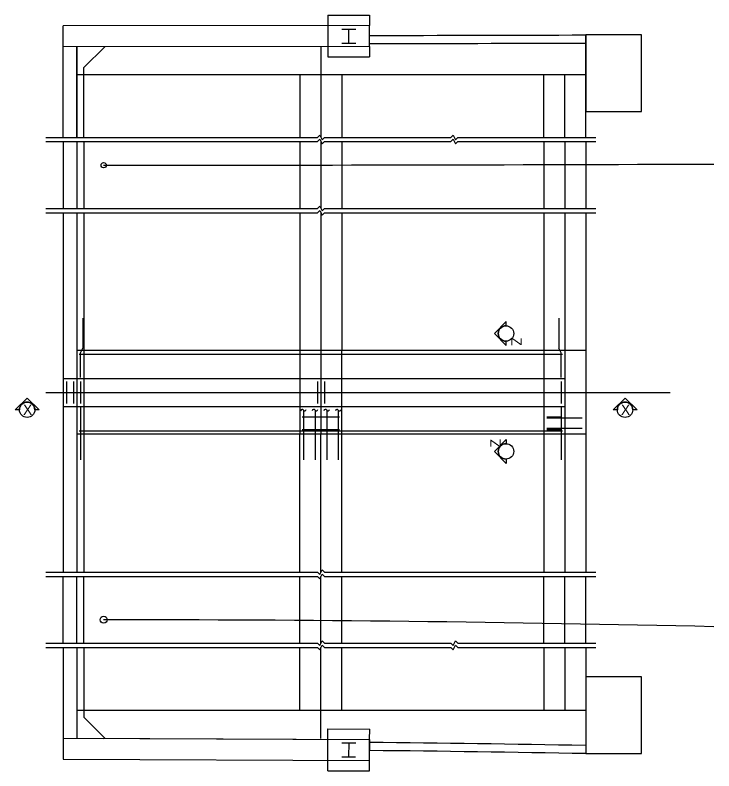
# Model space of a CAD drawing. Extents: x 1531 to 2925, y 1224 to 1658.
# Drawn here: x 2213.3 to 2263.4, y 1437.7 to 1491.9 of the extents above; entities that cross this region are included whole.
import ezdxf

# ---------------------------------------------------------------- set-up
doc = ezdxf.new("R2010")
doc.units = 0
for name, color, linetype in [('B_Border', 7, 'Continuous'), ('B_Reference_Clip', 7, 'Continuous'), ('BD-EXIST-COSS', 7, 'Continuous'), ('R_Border Prem', 7, 'Continuous'), ('R_Draft', 7, 'Continuous'), ('R_Guard Rail', 7, 'Continuous'), ('R_ROW_COA', 7, 'Continuous'), ('R_Survey Control', 7, 'Continuous'), ('R_Wall', 7, 'Continuous')]:
    doc.layers.add(name, color=color, linetype=linetype)

msp = doc.modelspace()

# ---------------------------------------------------------------- linework, layer by layer
at = {"layer": 'B_Border'}
msp.add_line((2215.527, 1464.865), (2260.321, 1464.865), dxfattribs=at)
at = {"layer": 'B_Reference_Clip'}
for points in [[(2258.25, 1490.511), (2254.25, 1490.511), (2254.25, 1485.011), (2258.25, 1485.011)], [(2258.25, 1444.457), (2254.25, 1444.457), (2254.25, 1438.957), (2258.25, 1438.957)]]:
    msp.add_lwpolyline(points, close=True, dxfattribs=at)
at = {"layer": 'BD-EXIST-COSS'}
for p, q in [((2218.167, 1470.199), (2218.167, 1468.032)), ((2252.333, 1470.199), (2252.333, 1468.032)), ((2217.917, 1467.615), (2252.583, 1467.615)), ((2218, 1467.699), (2218.167, 1468.032)), ((2218, 1465.949), (2218, 1467.699)), ((2252.5, 1467.699), (2252.333, 1468.032)), ((2252.5, 1465.949), (2252.5, 1467.699)), ((2217, 1465.647), (2217, 1464.084)), ((2217.5, 1465.647), (2217.5, 1464.084)), ((2218, 1465.647), (2218, 1464.084)), ((2235, 1465.647), (2235, 1464.084)), ((2235.5, 1465.647), (2235.5, 1464.084)), ((2252.5, 1465.647), (2252.5, 1464.084)), ((2218, 1463.782), (2218, 1460.032)), ((2234, 1463.6), (2234, 1460.032)), ((2234.833, 1463.6), (2234.833, 1460.032)), ((2235.667, 1463.6), (2235.667, 1460.032)), ((2236.5, 1463.6), (2236.5, 1460.032)), ((2252.5, 1463.782), (2252.5, 1460.032)), ((2233.917, 1463.115), (2236.583, 1463.115)), ((2251.458, 1463.115), (2252.542, 1463.115)), ((2251.458, 1463.032), (2254, 1463.032)), ((2233.917, 1462.215), (2236.583, 1462.215)), ((2251.458, 1462.299), (2254, 1462.299)), ((2251.458, 1462.215), (2252.542, 1462.215)), ((2217.917, 1462.115), (2252.583, 1462.115))]:
    msp.add_line(p, q, dxfattribs=at)
for centre, start, end in [((2233.907, 1463.546), 30.2608, 174.7876), ((2234.093, 1463.654), 210.2606, 354.7867), ((2234.741, 1463.546), 30.2608, 174.7876), ((2234.926, 1463.654), 210.2606, 354.7867), ((2235.574, 1463.546), 30.2608, 174.7876), ((2235.759, 1463.654), 210.2606, 354.7867), ((2236.407, 1463.546), 30.2608, 174.7876), ((2236.593, 1463.654), 210.2606, 354.7867)]:
    msp.add_arc(centre, 0.107, start, end, dxfattribs=at)
at = {"layer": 'R_Border Prem'}
for p, q in [((2238.75, 1489.683), (2238.749, 1490.474)), ((2254.25, 1487.667), (2254.25, 1490.511)), ((2238.75, 1489.683), (2217.75, 1489.667)), ((2217.75, 1489.667), (2217.75, 1487.667)), ((2235.25, 1489.68), (2235.25, 1487.667)), ((2217.75, 1487.667), (2254.25, 1487.667)), ((2254.25, 1467.865), (2217.75, 1467.865)), ((2217.75, 1467.865), (2217.75, 1465.865)), ((2233.75, 1467.865), (2233.75, 1461.865)), ((2235.25, 1467.865), (2235.25, 1461.865)), ((2236.75, 1461.865), (2236.75, 1467.865)), ((2251.25, 1467.865), (2251.25, 1461.865)), ((2252.75, 1467.865), (2252.75, 1461.865)), ((2254.25, 1467.865), (2254.25, 1461.865)), ((2217.75, 1465.865), (2217.75, 1463.865)), ((2217.75, 1463.865), (2217.75, 1461.865)), ((2254.25, 1461.865), (2217.75, 1461.865)), ((2217.75, 1442.064), (2254.25, 1442.064)), ((2217.75, 1442.064), (2217.75, 1440.06)), ((2235.25, 1440.051), (2235.25, 1442.064)), ((2254.25, 1442.064), (2254.25, 1438.957)), ((2217.75, 1440.06), (2219.667, 1440.051)), ((2217.75, 1440.06), (2238.75, 1439.968)), ((2238.75, 1439.968), (2238.746, 1439.176))]:
    msp.add_line(p, q, dxfattribs=at)
for centre, radius, start, end in [((2219.667, 12935.906), 11445.448, 270.0955282, 270.1731241), ((2219.667, 12935.323), 11445.448, 270.0955303, 270.1731241), ((2219.667, -456.504), 1896.359, 88.955591, 89.423449), ((2219.667, -457.087), 1896.359, 88.955056, 89.423525)]:
    msp.add_arc(centre, radius, start, end, dxfattribs=at)
at = {"layer": 'R_Draft'}
for p, q in [((2216.75, 1465.865), (2252.75, 1465.865)), ((2216.75, 1465.865), (2216.75, 1463.865)), ((2252.75, 1465.865), (2252.75, 1463.865)), ((2216.75, 1463.865), (2252.75, 1463.865))]:
    msp.add_line(p, q, dxfattribs=at)
at = {"layer": 'R_Guard Rail'}
for p, q in [((2235.748, 1491.93), (2238.748, 1491.933)), ((2235.748, 1491.93), (2235.749, 1491.18)), ((2238.748, 1491.933), (2238.749, 1491.183)), ((2238.749, 1491.183), (2216.75, 1491.167)), ((2216.75, 1483.16), (2216.75, 1491.167)), ((2235.749, 1491.18), (2235.75, 1489.68)), ((2236.749, 1490.931), (2237.749, 1490.932)), ((2237.25, 1489.931), (2237.249, 1490.931)), ((2238.75, 1489.683), (2238.749, 1491.183)), ((2236.75, 1489.931), (2237.75, 1489.932)), ((2238.75, 1489.683), (2216.75, 1489.667)), ((2217.75, 1483.16), (2217.75, 1489.667)), ((2219.75, 1489.667), (2218.25, 1488.167)), ((2235.75, 1489.68), (2235.751, 1488.93)), ((2238.75, 1489.683), (2238.751, 1488.933)), ((2235.751, 1488.93), (2238.751, 1488.933)), ((2217.75, 1485.46), (2217.75, 1487.667)), ((2217.75, 1487.667), (2217.75, 1483.16)), ((2218.25, 1483.16), (2218.25, 1488.167)), ((2233.75, 1487.667), (2233.75, 1483.16)), ((2235.25, 1487.667), (2235.25, 1483.16)), ((2236.75, 1487.667), (2236.75, 1483.16)), ((2251.25, 1483.16), (2251.25, 1487.667)), ((2252.75, 1483.16), (2252.75, 1487.667)), ((2254.25, 1483.16), (2254.25, 1487.667)), ((2216.75, 1482.86), (2216.75, 1478.06)), ((2217.75, 1482.86), (2217.75, 1478.06)), ((2217.75, 1482.86), (2217.75, 1478.06)), ((2218.25, 1482.86), (2218.25, 1478.06)), ((2233.75, 1482.86), (2233.75, 1478.06)), ((2235.25, 1482.86), (2235.25, 1478.06)), ((2236.75, 1482.86), (2236.75, 1478.06)), ((2251.25, 1482.86), (2251.25, 1478.06)), ((2252.75, 1482.86), (2252.75, 1478.06)), ((2254.25, 1482.86), (2254.25, 1478.06)), ((2216.75, 1477.76), (2216.75, 1451.971)), ((2217.75, 1477.76), (2217.75, 1467.865)), ((2218.25, 1477.76), (2218.25, 1451.971)), ((2233.75, 1477.76), (2233.75, 1467.865)), ((2235.25, 1477.793), (2235.25, 1467.865)), ((2236.75, 1477.76), (2236.75, 1467.865)), ((2251.25, 1477.76), (2251.25, 1467.865)), ((2252.75, 1477.76), (2252.75, 1467.865)), ((2254.25, 1477.76), (2254.25, 1467.865)), ((2217.75, 1472.36), (2217.75, 1451.971)), ((2217.75, 1467.865), (2217.75, 1461.865)), ((2217.75, 1461.865), (2217.75, 1451.971)), ((2233.75, 1451.971), (2233.75, 1461.865)), ((2235.25, 1451.971), (2235.25, 1461.865)), ((2236.75, 1451.971), (2236.75, 1461.865)), ((2251.25, 1461.865), (2251.25, 1451.971)), ((2252.75, 1461.865), (2252.75, 1451.971)), ((2254.25, 1461.865), (2254.25, 1451.971)), ((2216.75, 1446.871), (2216.75, 1451.671)), ((2217.75, 1446.871), (2217.75, 1451.671)), ((2217.75, 1446.871), (2217.75, 1451.671)), ((2218.25, 1446.871), (2218.25, 1451.671)), ((2233.75, 1446.871), (2233.75, 1451.671)), ((2235.25, 1446.821), (2235.25, 1451.671)), ((2236.75, 1446.871), (2236.75, 1451.671)), ((2251.25, 1446.871), (2251.25, 1451.671)), ((2252.75, 1446.871), (2252.75, 1451.671)), ((2254.25, 1446.871), (2254.25, 1451.671)), ((2216.75, 1446.571), (2216.75, 1438.564)), ((2217.75, 1446.571), (2217.75, 1442.064)), ((2217.75, 1446.571), (2217.75, 1440.064)), ((2218.25, 1446.571), (2218.25, 1441.564)), ((2233.75, 1442.064), (2233.75, 1446.571)), ((2235.25, 1442.064), (2235.25, 1446.571)), ((2236.75, 1442.064), (2236.75, 1446.571)), ((2251.25, 1446.571), (2251.25, 1442.064)), ((2252.75, 1446.571), (2252.75, 1442.064)), ((2254.25, 1446.571), (2254.25, 1442.064)), ((2219.75, 1440.064), (2218.25, 1441.564)), ((2235.75, 1439.981), (2235.753, 1440.731)), ((2235.753, 1440.731), (2238.753, 1440.718)), ((2238.75, 1439.968), (2238.753, 1440.718)), ((2216.75, 1440.064), (2238.75, 1439.968)), ((2235.743, 1438.481), (2235.75, 1439.981)), ((2238.743, 1438.468), (2238.75, 1439.968)), ((2236.749, 1439.727), (2237.749, 1439.722)), ((2237.249, 1439.725), (2237.244, 1438.725)), ((2216.75, 1438.564), (2238.743, 1438.468)), ((2235.74, 1437.731), (2235.743, 1438.481)), ((2236.744, 1438.727), (2237.744, 1438.722)), ((2238.74, 1437.718), (2238.743, 1438.468)), ((2235.74, 1437.731), (2238.74, 1437.718))]:
    msp.add_line(p, q, dxfattribs=at)
at = {"layer": 'R_ROW_COA'}
for centre, radius, start, end in [((2219.667, 12940.323), 11459.156, 270.0000001, 270.2189058), ((2219.667, -461.3), 1909.859, 88.686453, 90)]:
    msp.add_arc(centre, radius, start, end, dxfattribs=at)
at = {"layer": 'R_Survey Control'}
for points in [[(2248.533, 1469.647), (2248.533, 1469.955), (2247.707, 1469.095), (2248.533, 1468.235), (2248.533, 1468.542)], [(2213.621, 1463.622), (2213.314, 1463.622), (2214.173, 1464.448), (2215.033, 1463.622), (2214.726, 1463.622)], [(2256.52, 1463.622), (2256.213, 1463.622), (2257.073, 1464.448), (2257.932, 1463.622), (2257.625, 1463.622)], [(2248.533, 1460.083), (2248.533, 1459.776), (2247.707, 1460.636), (2248.533, 1461.495), (2248.533, 1461.188)]]:
    msp.add_lwpolyline(points, dxfattribs=at)
for centre in [(2248.533, 1469.093), (2214.176, 1463.622), (2257.073, 1463.622), (2248.533, 1460.638)]:
    msp.add_circle(centre, 0.552, dxfattribs=at)
for centre, start, end in [((2248.533, 1469.095), 90, 270), ((2214.173, 1463.622), 0, 180), ((2257.073, 1463.622), 0, 180), ((2248.533, 1460.636), 90, 270)]:
    msp.add_arc(centre, 0.552, start, end, dxfattribs=at)
at = {"layer": 'R_Wall'}
for p, q in [((2235, 1483.16), (2235.167, 1483.326)), ((2235.167, 1483.326), (2235.333, 1482.993)), ((2244.576, 1483.16), (2244.743, 1483.326)), ((2244.743, 1483.326), (2244.909, 1482.993)), ((2215.527, 1483.16), (2235, 1483.16)), ((2215.527, 1482.86), (2235, 1482.86)), ((2235, 1482.86), (2235.167, 1483.026)), ((2235.167, 1483.026), (2235.333, 1482.693)), ((2235.333, 1482.993), (2235.5, 1483.16)), ((2235.333, 1482.693), (2235.5, 1482.86)), ((2235.5, 1483.16), (2244.576, 1483.16)), ((2235.5, 1482.86), (2244.576, 1482.86)), ((2244.576, 1482.86), (2244.743, 1483.026)), ((2244.743, 1483.026), (2244.909, 1482.693)), ((2244.909, 1482.993), (2245.076, 1483.16)), ((2244.909, 1482.693), (2245.076, 1482.86)), ((2245.076, 1483.16), (2254.973, 1483.16)), ((2245.076, 1482.86), (2254.973, 1482.86)), ((2215.527, 1478.06), (2235, 1478.06)), ((2235, 1478.06), (2235.167, 1478.226)), ((2235, 1477.76), (2235.167, 1477.926)), ((2235.167, 1478.226), (2235.333, 1477.893)), ((2235.167, 1477.926), (2235.333, 1477.593)), ((2235.333, 1477.893), (2235.5, 1478.06)), ((2235.5, 1478.06), (2254.973, 1478.06)), ((2215.527, 1477.76), (2235, 1477.76)), ((2235.333, 1477.593), (2235.5, 1477.76)), ((2235.5, 1477.76), (2254.973, 1477.76)), ((2215.527, 1451.971), (2235, 1451.971)), ((2235, 1451.971), (2235.167, 1451.804)), ((2235.167, 1451.804), (2235.333, 1452.138)), ((2235.333, 1452.138), (2235.5, 1451.971)), ((2235.5, 1451.971), (2254.973, 1451.971)), ((2215.527, 1451.671), (2235, 1451.671)), ((2235, 1451.671), (2235.167, 1451.504)), ((2235.167, 1451.504), (2235.333, 1451.838)), ((2235.333, 1451.838), (2235.5, 1451.671)), ((2235.5, 1451.671), (2254.973, 1451.671)), ((2235.167, 1446.704), (2235.333, 1447.038)), ((2235.333, 1447.038), (2235.5, 1446.871)), ((2244.743, 1446.704), (2244.909, 1447.038)), ((2244.909, 1447.038), (2245.076, 1446.871)), ((2215.527, 1446.871), (2235, 1446.871)), ((2215.527, 1446.571), (2235, 1446.571)), ((2235, 1446.871), (2235.167, 1446.704)), ((2235, 1446.571), (2235.167, 1446.404)), ((2235.167, 1446.404), (2235.333, 1446.738)), ((2235.333, 1446.738), (2235.5, 1446.571)), ((2235.5, 1446.871), (2244.576, 1446.871)), ((2235.5, 1446.571), (2244.576, 1446.571)), ((2244.576, 1446.871), (2244.743, 1446.704)), ((2244.576, 1446.571), (2244.743, 1446.404)), ((2244.743, 1446.404), (2244.909, 1446.738)), ((2244.909, 1446.738), (2245.076, 1446.571)), ((2245.076, 1446.871), (2254.973, 1446.871)), ((2245.076, 1446.571), (2254.973, 1446.571))]:
    msp.add_line(p, q, dxfattribs=at)
for centre, radius in [((2219.667, 1481.167), 0.188), ((2219.667, 1448.56), 0.25)]:
    msp.add_circle(centre, radius, dxfattribs=at)

# ---------------------------------------------------------------- texts
at = {"layer": 'R_Survey Control'}
for s, rotation, p in [('Z', 270, (2248.908, 1468.82)), ('X', 360, (2213.879, 1463.247)), ('X', 360, (2256.775, 1463.247)), ('Z', 90, (2248.158, 1460.91))]:
    msp.add_text(s, height=0.75, rotation=rotation, dxfattribs=at).set_placement(p)

doc.saveas('drawing.dxf')
